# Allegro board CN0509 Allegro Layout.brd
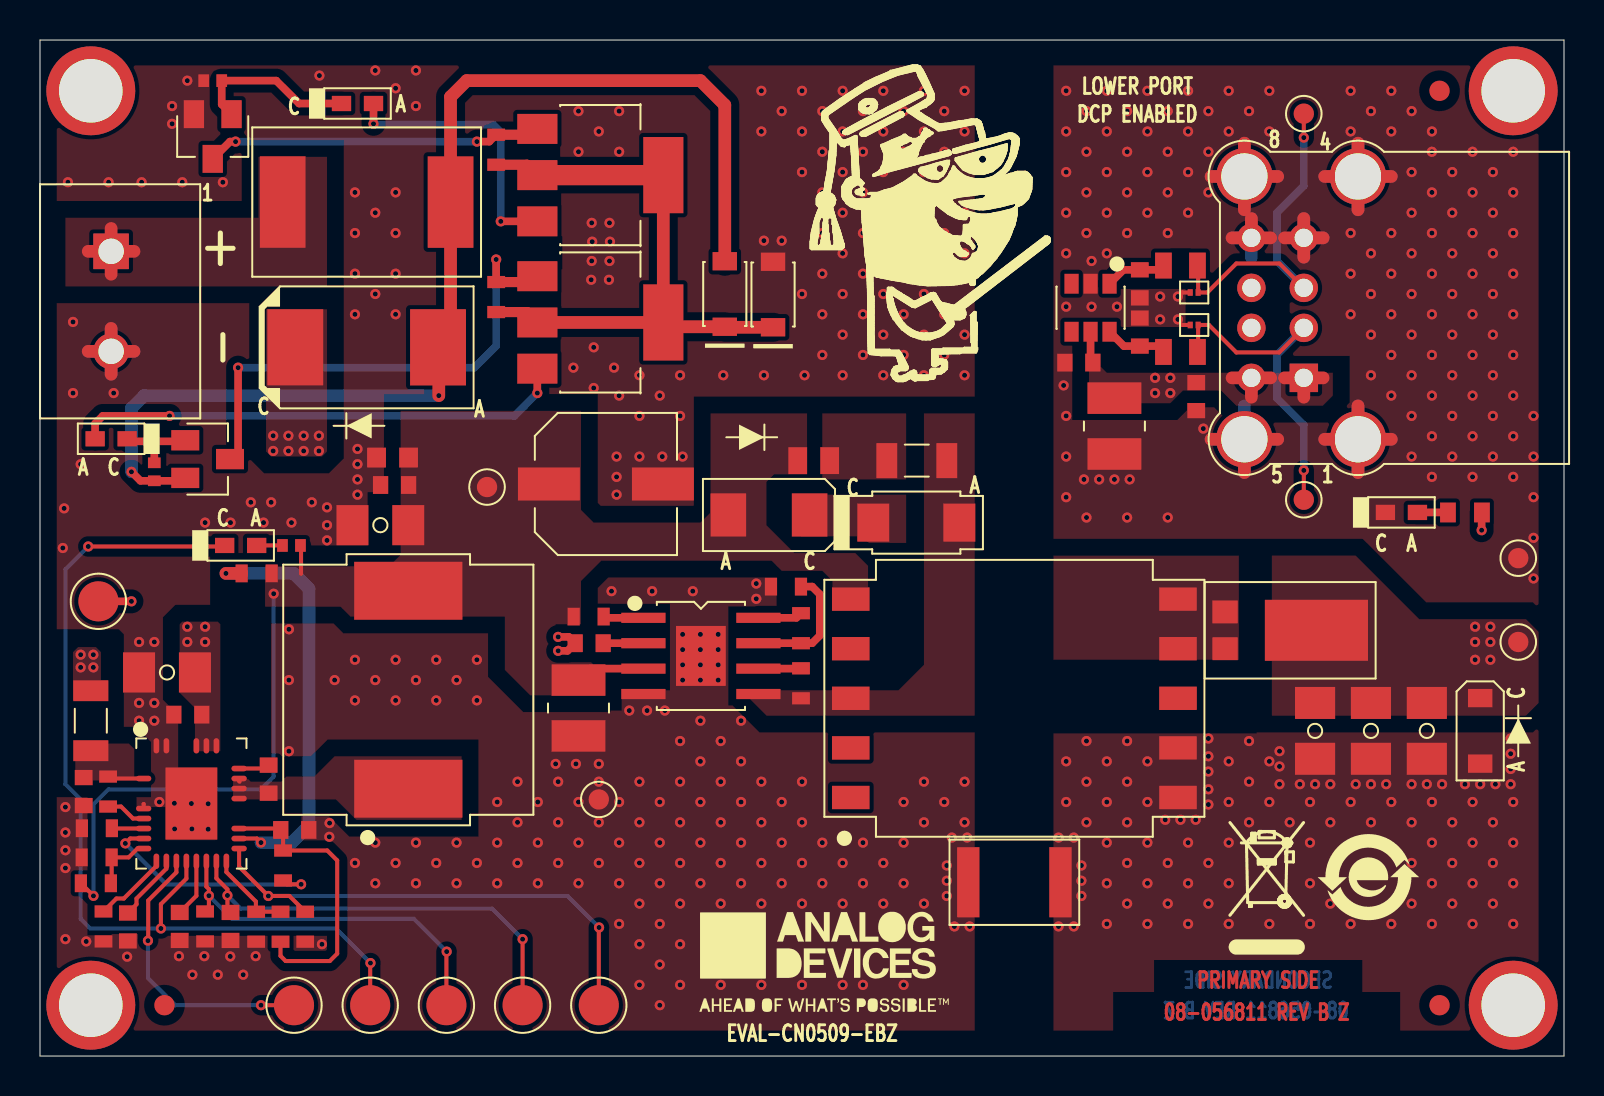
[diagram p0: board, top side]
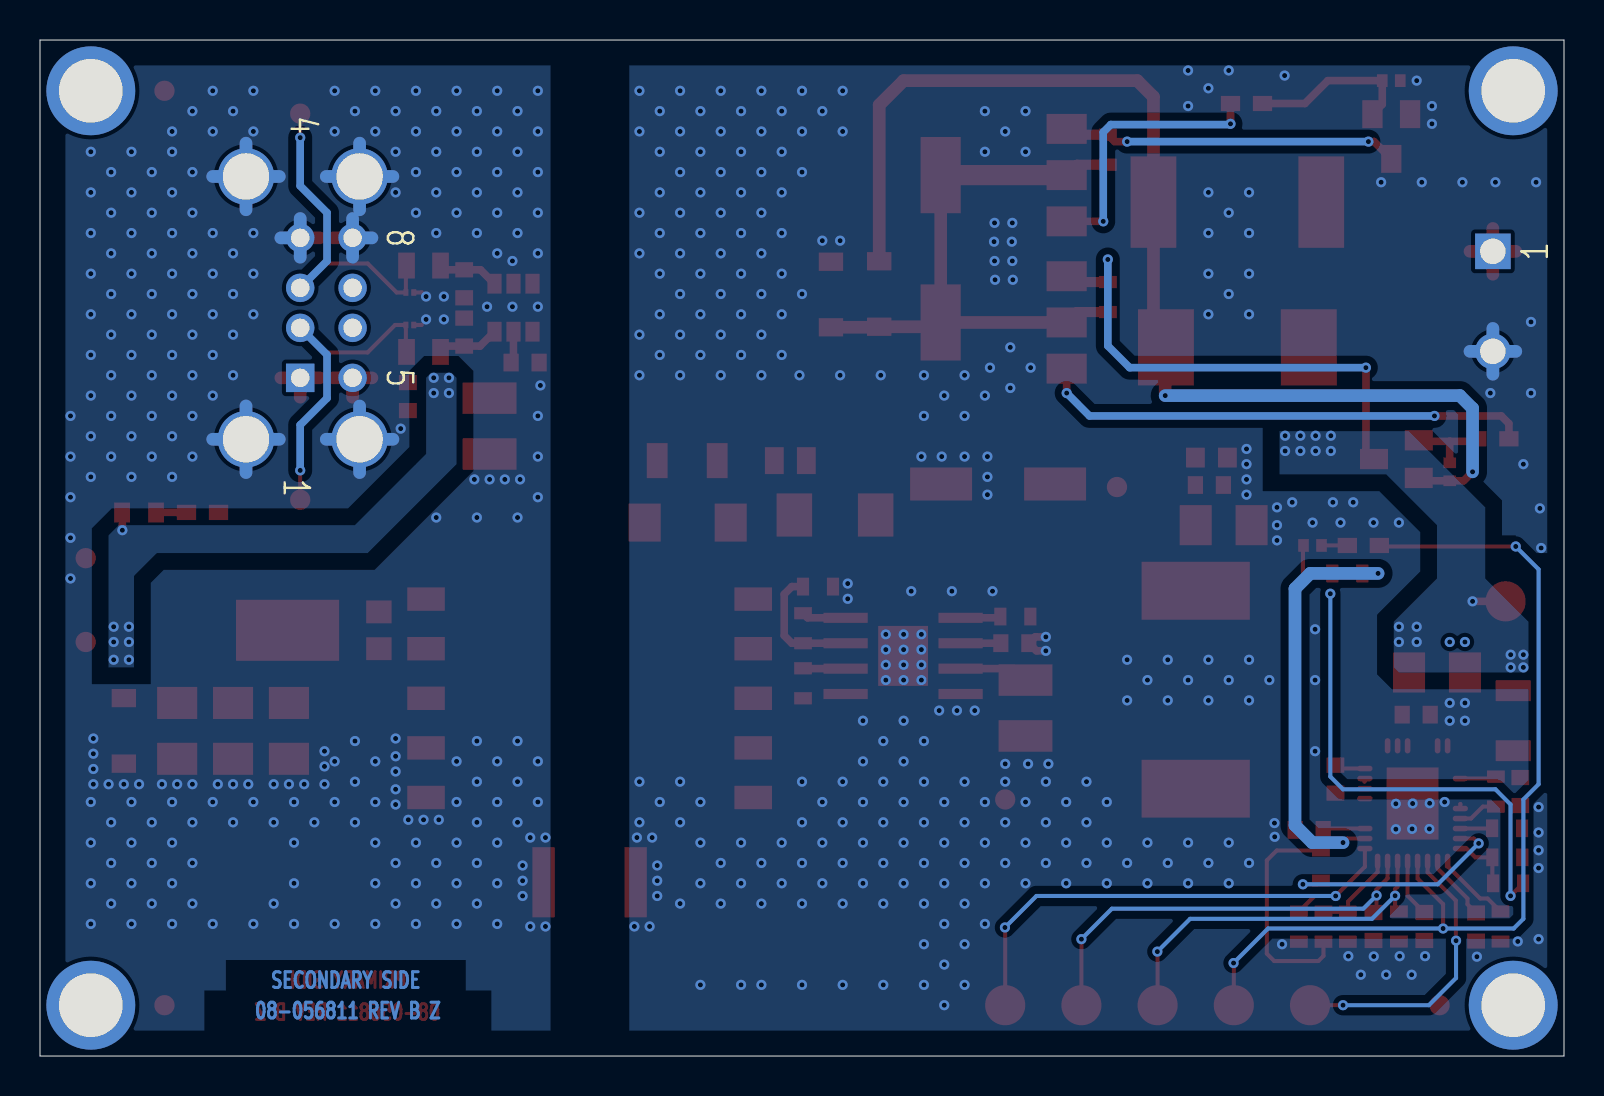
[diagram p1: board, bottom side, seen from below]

Outline 76.2 x 50.8 mm; copper layers: TOP, L2_GND, L3_GND, BOTTOM. Coordinates in mm from the lower left corner of the outline.
Outline path: 0,50.8 0,0 76.2,0 76.2,50.8 0,50.8

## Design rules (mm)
constraint set DEFAULT: min track width 0.203

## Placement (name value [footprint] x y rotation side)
C1  1uF  [C0603]  12.74 11.3 180 top
C2  4.7uF  [C1206H71]  6.35 19.18 0 top
C3  0.1uF  [C0603]  11.43 13.84 90 top
C4  0.1uF  [C0603]  7.39 17.07 0 top
C5  0.1uF  [C0603]  4.39 6.45 90 top
C6  22uF  [CPLSMSQ260H315]  28.3 28.6 0 top
C7  10uF  [C1210-2]  26.92 17.4 90 top
C8  100uF  [C1206H71]  17.02 26.54 0 top
C9  0.1uF  [C0603]  17.73 28.55 0 top
C10  0.1uF  [C0603]  9.53 6.48 90 top
C11  1uF  [C0603#2]  17.63 29.92 0 top
C12  0.1uF  [C0603]  6.99 6.48 90 top
C13  0.1uF  [C0603]  2.18 13.22 90 top
C14  1uF  [C0603]  27.46 20.64 0 top
C15  220pF  [C0805]  38.68 29.77 180 top
C16  100uF  [C1206H71]  63.75 16.26 90 top
C17  100uF  [C1206H71]  66.55 16.26 90 top
C18  100uF  [C1206H71]  69.34 16.26 90 top
C19  4700pF  [C1812H79]  48.72 8.69 0 top
C20  10uF  [C1210-2]  53.72 31.5 90 top
C21  0.01uF  [C0603]  51.94 34.67 0 top
C22  1000pF  [C0603]  54.99 38.61 90 top
C23  1000pF  [C0603]  54.99 36.2 270 top
C24  1uF  [C0603]  57.81 32.97 90 top
CLKOUT  SMOX/060/B1/R2K GOLD  [CNOXLEYSMOX_060_B1]  12.7 2.54 0 top
D1  PDS1040L  [POWERDI5]  62.51 21.28 270 top
D2  SMD1200PL-TP  [SOD123FLH53]  36.65 38.07 90 top
D3  SMAJ18A-13-F  [DO214AC]  36.45 27.05 180 top
D4  SS110FL-TP  [DO221AC_SMA-FL]  43.81 26.67 0 top
D5  MMSZ5232B-7-F  [SOD123-2]  72.01 16.26 270 top
D6  SMD1200PL-TP  [SOD123FLH53]  34.24 38.1 90 top
D7  MBRS3201T3G  [SMC]  16.33 35.43 0 top
D8  ESD230B1W0201E6327XTSA1  [D0201H6]  57.71 36.55 0 top
D9  ESD230B1W0201E6327XTSA1  [D0201H6]  57.71 38.18 0 top
D+  TESTPAD  [TPSMC40]  63.19 47.12 0 top
D-  TESTPAD  [TPSMC40]  63.19 27.81 0 top
DS1  LTST-C190CKT  [LED0603]  3.56 30.86 180 top
DS2  LTST-C190GKT  [LED0603]  15.88 47.62 0 top
DS3  LTST-C190GKT  [LED0603]  10.03 25.53 0 top
DS4  LTST-C190GKT  [LED0603]  68.07 27.18 0 top
F1  2.5A  [SMD250F]  16.33 42.7 0 top
GND  TESTPAD  [TPSMC40]  73.91 24.89 0 top
GND1  TESTPAD  [TPSMC40]  27.94 12.83 0 top
ICTRL  SMOX/060/B1/R2K GOLD  [CNOXLEYSMOX_060_B1]  20.32 2.54 0 top
IMON  SMOX/060/B1/R2K GOLD  [CNOXLEYSMOX_060_B1]  24.13 2.54 0 top
L1  47UH  [LSMSQ472H394]  18.41 18.31 90 top
NOREF  -  []  0 50.8 0 top
NOREF#2  -  []  0 50.8 0 top
NOREF#3  -  [unnamed#2]  2.54 2.54 0 top
NOREF#4  -  []  0 0 0 top
NOREF#5  -  []  38.91 4.67 0 top
NOREF#6  -  []  76.2 0 0 top
NOREF#7  -  []  74.43 49.27 0 top
NOREF#8  -  []  -63.5 226.06 0 top
NOREF#9  -  []  2.54 2.54 0 top
NOREF#10  -  []  0 50.8 270 top
NOREF#11  -  []  32.21 -14.22 270 top
NOREF#12  -  [unnamed#2]  69.98 2.54 0 top
NOREF#13  -  []  0 0 0 top
NOREF#14  -  []  -86.36 181.61 0 top
NOREF#15  -  []  61.14 5.13 0 top
NOREF#16  -  [unnamed#2]  73.66 2.54 0 top
NOREF#17  -  [unnamed#2]  6.22 2.54 0 top
NOREF#18  -  []  0 0 0 top
NOREF#19  -  []  2.54 2.54 0 top
NOREF#20  -  [unnamed#2]  2.54 48.26 0 top
NOREF#21  -  []  -42.55 -32 0 top
NOREF#22  -  []  -124.46 -144.78 0 top
NOREF#23  -  []  132.97 172.34 0 top
NOREF#24  -  []  -124.46 -144.78 0 top
NOREF#25  -  []  76.2 50.8 180 top
NOREF#26  -  []  76.2 0 90 top
NOREF#27  -  []  76.2 0 90 top
NOREF#28  -  [unnamed#2]  69.98 48.26 0 top
NOREF#29  -  []  66.42 8.94 0 top
NOREF#30  -  []  115.57 44.7 0 top
NOREF#31  -  [unnamed#2]  73.66 48.26 0 top
NOREF#32  -  []  -124.46 -144.78 0 top
NOREF#33  -  []  280.77 319.28 0 top
NOREF#34  -  []  76.2 40.95 0 top
P1  OSTTC020162  [CNOSTTC0201X2]  3.56 40.23 270 top
P2  UJ2-ADH-1-TH  [CNCUIUJ2-ADH-X-TH]  63.19 33.91 90 top
PGOOD  SMOX/060/B1/R2K GOLD  [CNOXLEYSMOX_060_B1]  16.51 2.54 0 top
Q1  MMBT3904LT1G  [SOT23]  8.64 45.97 180 top
Q2  MMBT3904LT1G  [SOT23]  8.38 29.84 270 top
Q3  DZTA42-13  [SOT223-3]  28.02 44.04 270 top
Q4  DZTA42-13  [SOT223-3]  28.02 36.68 270 top
R1  270K  [R0603]  22.81 45.31 270 top
R2  240  [R0603#2]  8.64 48.77 0 top
R3  270K  [R0603]  22.81 37.95 270 top
R4  240  [R0603#2]  5.71 29.21 90 top
R5  0  [R0603]  12.03 6.46 90 top
R6  0  [R0603]  10.81 6.46 270 top
R7  10MEG  [R1206]  2.54 16.76 90 top
R8  0  [R0603]  12.15 9.53 270 top
R9  0  [R0603]  10.83 24.13 0 top
R10  0  [R0603]  3.4 13.22 90 top
R11  0  [R0603]  3.17 6.48 90 top
R12  0  [R0603]  2.79 8.64 180 top
R13  0  [R0603]  2.83 9.93 180 top
R14  10K  [R0603]  37.3 23.47 0 top
R15  1MEG  [R0603]  27.43 21.97 180 top
R16  0  [R0603]  2.84 11.39 180 top
R17  0  [R0603]  8.25 6.48 270 top
R18  0  [R0603]  13.26 6.46 270 top
R19  100  [R1206]  43.84 29.77 180 top
R20  158K  [R0603]  38.05 18.63 90 top
R21  113K  [R0603]  38.05 21.39 270 top
R22  24  [R0805]  57.02 35.2 0 top
R23  24  [R0805]  57.02 39.52 0 top
R24  3.48K  [R0603#2]  12.57 25.53 0 top
R25  2.1K  [R0603]  71.25 27.18 0 top
T1  750311564  [TSMSQ525H500]  48.72 17.88 0 top
TP1  SMOX/060/B1/R2K GOLD  [CNOXLEYSMOX_060_B1]  27.94 2.54 0 top
TP6  SMOX/060/B1/R2K GOLD  [CNOXLEYSMOX_060_B1]  2.92 22.73 0 top
U1  LTC7103EUHE#PBF  [QFN36_5X6_PAD2_6X3_6]  7.57 12.62 270 top
U2  LT8302IS8E#PBF  [SO8NB_PAD3X2_49]  33.05 20 270 top
U3  TPS2514DBVR  [SOT23_6-2]  52.53 37.41 180 top
UNK12V  TESTPAD  [TPSMC40]  22.35 28.45 0 top
VBUS  TESTPAD  [TPSMC40]  73.91 20.7 0 top

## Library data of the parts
C1 C11 C14 C24 = CAP: User Part Number: UPN; Tolerance: 10; alternate symbols: C0603L; part number: CAP_SM-1UF,50V,10,E034224,C0603; tolerance: 10
C2 = CAP: Tolerance: 10; User Part Number: UPN; alternate symbols: (); part number: CAP_SM-4.7UF,100V,10,E034771,C1206H71; tolerance: 10
C3-C5 C9 C10 C12 C13 = CAP: User Part Number: UPN; Tolerance: 10; alternate symbols: C0603L; part number: CAP_SM-0.1UF,100V,10,E033337,C0603; tolerance: 10
C6 = CAPP: Tolerance: 20; User Part Number: UPN; alternate symbols: (); part number: CAPP_SM-22UF,63V,20,E034289,CPLSMSQ260H315; tolerance: 20
C7 C20 = CAP: Tolerance: 10; User Part Number: UPN; alternate symbols: (); part number: CAP_SM-10UF,50V,10,E038290,C1210-2; tolerance: 10
C8 C16-C18 = CAP: Tolerance: 10; User Part Number: UPN; alternate symbols: (); part number: CAP_SM-100UF,6.3V,10,E039989,C1206H71; tolerance: 10
C15 = CAP: User Part Number: UPN; Tolerance: 5; alternate symbols: C0805L; part number: CAP_SM-220PF,50V,5,E000453,C0805; tolerance: 5
C19 = CAP: Tolerance: 10; User Part Number: UPN; alternate symbols: (); part number: CAP_SM-4700PF,150V,10,E039988,C1812H79; tolerance: 10
C21 = CAP: User Part Number: UPN; Tolerance: 10; alternate symbols: C0603L; part number: CAP_SM-0.01UF,100V,10,E032297,C0603; tolerance: 10
C22 C23 = CAP: User Part Number: UPN; Tolerance: 10; alternate symbols: C0603L; part number: CAP_SM-1000PF,50V,10,E013782,C0603; tolerance: 10
CLKOUT ICTRL IMON PGOOD TP1 TP6 = CNTP1P: Tolerance: N/A; User Part Number: UPN; alternate symbols: (); part number: CNTP1P_SM-GOLD,E023771,CNOXLEYSMOX_060_B1; tolerance: N/A
D1 = DIOSCHOTTKY_3P: Tolerance: N/A; User Part Number: UPN; alternate symbols: (); part number: DIOSCHOTTKY_3P_SM-PDS1040L,40V,N/A,E006430,POWERDI5; tolerance: N/A
D2 D6 = DIOSCHOTTKY: User Part Number: UPN; Tolerance: N/A; alternate symbols: (); part number: DIOSCHOTTKY_SM-SMD1200PL-TP,200V,N/A,E042391,SOD123FLH53; tolerance: N/A
D3 = DIO: User Part Number: UPN; Tolerance: N/A; alternate symbols: (); part number: DIO_SM-SMAJ18A-13-F,N/A,N/A,E006682,DO214AC; tolerance: N/A
D4 = DIOSCHOTTKY: User Part Number: UPN; Tolerance: N/A; alternate symbols: (); part number: DIOSCHOTTKY_SM-SS110FL-TP,100V,N/A,E039987,DO221AC_SMA-FL; tolerance: N/A
D5 = DIOZNR: User Part Number: UPN; Tolerance: N/A; alternate symbols: (); part number: DIOZNR_SM-MMSZ5232B-7-F,5.6V,N/A,E039990,SOD123-2; tolerance: N/A
D7 = DIOSCHOTTKY: User Part Number: UPN; Tolerance: N/A; alternate symbols: (); part number: DIOSCHOTTKY_SM-MBRS3201T3G,200V,N/A,E014312,SMC; tolerance: N/A
D8 D9 = DIOZNR_V2: User Part Number: UPN; Tolerance: N/A; alternate symbols: (); part number: DIOZNR_V2_SM-ESD230B1W0201E6327XTSA1,5.5V,N/A,E040149,D0201H6; tolerance: N/A
D+ D- GND GND1 UNK12V VBUS = NCTESTPAD: Tolerance: N/A; User Part Number: UPN; alternate symbols: (); part number: NCTESTPAD_SM-TESTPAD,E019801,TPSMC40; tolerance: N/A
DS1 = DIOLED: Tolerance: N/A; User Part Number: UPN; alternate symbols: (); part number: DIOLED_SM-LTST-C190CKT,N/A,N/A,E023763,LED0603; tolerance: N/A
DS2-DS4 = DIOLED: Tolerance: N/A; User Part Number: UPN; alternate symbols: (); part number: DIOLED_SM-LTST-C190GKT,N/A,N/A,E006239,LED0603; tolerance: N/A
F1 = FSFUSE: Tolerance: N/A; User Part Number: UPN; alternate symbols: (); part number: FSFUSE_SM-2.5A,15V,E006334,SMD250F; tolerance: N/A
L1 = IND: Tolerance: 20; User Part Number: UPN; alternate symbols: (); part number: IND_SM-47UH,20,E041207,LSMSQ472H394; tolerance: 20
P1 = CN2P: Tolerance: N/A; User Part Number: UPN; alternate symbols: (); part number: CN2P_TH-OSTTC020162,E034806,CNOSTTC0201X2; tolerance: N/A
P2 = CN8P_4PSHLD: User Part Number: UPN; Tolerance: N/A; alternate symbols: (); part number: CN8P_4PSHLD_TH-UJ2-ADH-1-TH,E039589,CNCUIUJ2-ADH-X-TH; tolerance: N/A
Q1 Q2 = TRANMMBT4401: User Part Number: UPN; Tolerance: N/A; alternate symbols: (); part number: TRANMMBT4401_SM-MMBT3904LT1G,E004664,SOT23; tolerance: N/A
Q3 Q4 = TRANNPN_4P_V2: User Part Number: UPN; Tolerance: N/A; alternate symbols: (); part number: TRANNPN_4P_V2_SM-DZTA42-13,E039574,SOT223-3; tolerance: N/A
R1 R3 = RES: User Part Number: UPN; Tolerance: 1; alternate symbols: R0603L; part number: RES_SM-270K,E013325,1/10W,1,R0603; tolerance: 1
R2 R4 = RES: User Part Number: UPN; Tolerance: 1; alternate symbols: R0402L; part number: RES_SM-240,E044225,1/10W,1,R0603; tolerance: 1
R5 R6 R8-R13 R16-R18 = RES: User Part Number: UPN; Tolerance: JUMPER; alternate symbols: R0603L; part number: RES_SM-0,E006826,1/10W,JUMPER,R0603; tolerance: JUMPER
R7 = RES: User Part Number: UPN; Tolerance: 1; alternate symbols: (); part number: RES_SM-10MEG,E016426,1/4W,1,R1206; tolerance: 1
R14 = RES: User Part Number: UPN; Tolerance: 1; alternate symbols: R0603L; part number: RES_SM-10K,E003671,1/10W,1,R0603; tolerance: 1
R15 = RES: User Part Number: UPN; Tolerance: 1; alternate symbols: R0603L; part number: RES_SM-1MEG,E003682,1/10W,1,R0603; tolerance: 1
R19 = RES: User Part Number: UPN; Tolerance: 1; alternate symbols: (); part number: RES_SM-100,E003220,1/4W,1,R1206; tolerance: 1
R20 = RES: User Part Number: UPN; Tolerance: 1; alternate symbols: R0603L; part number: RES_SM-158K,E028116,1/10W,1,R0603; tolerance: 1
R21 = RES: User Part Number: UPN; Tolerance: 1; alternate symbols: R0603L; part number: RES_SM-113K,E021374,1/10W,1,R0603; tolerance: 1
R22 R23 = RES: User Part Number: UPN; Tolerance: 1; alternate symbols: R0805L; part number: RES_SM-24,E031456,1/8W,1,R0805; tolerance: 1
R24 = RES: User Part Number: UPN; Tolerance: 1; alternate symbols: R0402L; part number: RES_SM-3.48K,E003694,1/10W,1,R0603; tolerance: 1
R25 = RES: User Part Number: UPN; Tolerance: 1; alternate symbols: (R0603L); part number: RES_SM-2.1K,E011132,1/10W,1,R0603; tolerance: 1
T1 = XFMR10P_V14: User Part Number: UPN; Tolerance: N/A; alternate symbols: (); part number: XFMR10P_V14_SM-750311564,E039577,TSMSQ525H500; tolerance: N/A
U1 = ICLTC7103: Tolerance: N/A; User Part Number: UPN; alternate symbols: (); part number: ICLTC7103_SM-LTC7103EUHE#PBF,E033167,QFN36_5X6_PAD2_6X3_6; tolerance: N/A
U2 = LINLT8302: Tolerance: N/A; User Part Number: UPN; alternate symbols: (); part number: LINLT8302_SM-LT8302IS8E#PBF,E031116,SO8NB_PAD3X2_49; tolerance: N/A
U3 = ICTPS2514: User Part Number: UPN; Tolerance: N/A; alternate symbols: (); part number: ICTPS2514_SM-TPS2514DBVR,E035630,SOT23_6-2; tolerance: N/A

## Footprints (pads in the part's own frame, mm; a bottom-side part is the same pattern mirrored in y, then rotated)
C0603
  rect 0.762x0.889 smd: 1(-0.7,0) 2(0.7,0)
C0603#2
  rect 0.94x0.991 smd: 1(-0.8,0) 2(0.8,0)
C0805
  rect 0.94x1.346 smd: 1(-0.8,0) 2(0.8,0)
C1206H71
  rect 1.6x2.007 smd: 1(-1.397,0) 2(1.397,0)
C1210-2
  rect 1.575x2.692 smd: 1(-1.397,0) 2(1.397,0)
C1812H79
  rect 1.118x3.505 smd: 1(-2.304,0) 2(2.304,0)
CNCUIUJ2-ADH-X-TH
  rect 1.422x1.422 hole 0.914: 1(0,0)
  round 1.422 hole 0.914: 2(2.5,0) 3(4.5,0) 4(7,0) 5(0,2.62) 6(2.5,2.62) 7(4.5,2.62) 8(7,2.62)
  round 2.819 hole 2.311: SH1(-3.07,-2.71) SH2(10.07,-2.71) SH3(-3.07,2.97) SH4(10.07,2.97)
CNOSTTC0201X2
  rect 1.778x1.778 hole 1.27: 1(0,0)
  round 1.778 hole 1.27: 2(5,0)
CNOXLEYSMOX_060_B1
  round 2.007 smd: 1(0,0)
CPLSMSQ260H315
  rect 3.099x1.651 smd: N(2.85,0) P(-2.85,0)
D0201H6
  rect 0.254x0.33 smd: 1(-0.197,0) 2(0.197,0)
DO214AC
  rect 1.778x2.159 smd: A(2.032,0) C(-2.032,0)
DO221AC_SMA-FL
  rect 1.6x1.905 smd: A(2.15,0) C(-2.15,0)
LED0603
  rect 0.965x0.762 smd: A(0.8,0) C(-0.8,0)
LSMSQ472H394
  rect 2.896x5.41 smd: 1(-4.948,0) 2(4.948,0)
POWERDI5
  rect 1.143x1.27 smd: 1(-0.92,-3.255) 2(0.92,-3.255)
  rect 3.048x5.156 smd: 3(0,1.312)
QFN36_5X6_PAD2_6X3_6
  oval 0.279x0.762 smd: 3(-1.25,-2.386) 6(0.25,-2.386) 7(0.75,-2.386) 8(1.25,-2.386) 9(1.75,-2.386) 10(2.25,-2.386) 19(2.25,2.386) 20(1.75,2.386) 21(1.25,2.386) 24(-0.25,2.386) 25(-0.75,2.386) 26(-1.25,2.386) 27(-1.75,2.386)
  oval 0.762x0.279 smd: 11(2.886,-1.75) 12(2.886,-1.25) 13(2.886,-0.75) 14(2.886,-0.25) 15(2.886,0.25) 16(2.886,0.75) 17(2.886,1.25) 18(2.886,1.75) 30(-2.886,1.25) 31(-2.886,0.75) 32(-2.886,0.25) 35(-2.886,-1.25) 36(-2.886,-1.75)
  rect 3.607x2.591 smd: PAD(0,0)
R0603
  rect 0.61x0.889 smd: 1(-0.75,0) 2(0.75,0)
R0603#2
  rect 0.533x0.635 smd: 1(-0.45,0) 2(0.45,0)
R0805
  rect 0.838x1.295 smd: 1(-0.85,0) 2(0.85,0)
R1206
  rect 1.041x1.753 smd: 1(-1.5,0) 2(1.5,0)
SMC
  rect 2.794x3.81 smd: A(3.569,0) C(-3.569,0)
SMD250F
  rect 2.286x4.572 smd: 1(-4.196,0) 2(4.196,0)
SO8NB_PAD3X2_49
  rect 0.508x2.21 smd: 1(-1.905,-2.875) 2(-0.635,-2.875) 3(0.635,-2.875) 4(1.905,-2.875) 5(1.905,2.875) 6(0.635,2.875) 7(-0.635,2.875) 8(-1.905,2.875)
  rect 2.997x2.489 smd: PAD(0,0)
SOD123-2
  rect 0.914x1.219 smd: A(1.638,0) C(-1.638,0)
SOD123FLH53
  rect 0.914x1.219 smd: A(1.638,0) C(-1.638,0)
SOT23
  rect 1.016x1.397 smd: 1(-0.94,-1.118) 2(0.94,-1.118) 3(0,1.118)
SOT23_6-2
  rect 0.711x0.991 smd: 1(-0.95,-1.2) 2(0,-1.2) 3(0.95,-1.2) 4(0.95,1.2) 5(0,1.2) 6(-0.95,1.2)
SOT223-3
  rect 1.499x2.007 smd: 1(-2.311,-3.15) 2(0,-3.15) 3(2.311,-3.15)
  rect 3.81x2.007 smd: 4(0,3.15)
TPSMC40
  round 1.016 smd: 1(0,0)
TSMSQ525H500
  rect 1.88x1.168 smd: 1(-8.18,-4.96) 2(-8.18,-2.48) 3(-8.18,0) 4(-8.18,2.48) 5(-8.18,4.96) 6(8.18,4.96) 7(8.18,2.48) 8(8.18,0) 9(8.18,-2.48) 10(8.18,-4.96)
unnamed#2
  round 4.445 hole 3.175 unplated: (0,0)

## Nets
GND: C1.1 C2.1 C4.1 C5.1 C6.N(N2) C7.1 C8.1 C9.1 C10.1 C11.1 C12.1 C13.1 C14.1 C19.1 D2.A(P) GND1.1(N1) P1.2(N2) Q1.2(E) R2.1 R6.2(N2) R11.1 R13.2(N2) R14.1 R16.2(N2) R17.2(N2) R18.2(N2) U1.6 U1.35 U1.36 U1.PAD U2.4 U2.PAD
PGND: C16.1 C17.1 C18.1 C19.2(N2) C20.1 C21.1 C22.1 C23.1 C24.1 D5.A(P) D8.1 D9.1 DS4.C GND.1(N1) P2.4 P2.8 P2.SH1(N9) P2.SH2 P2.SH3 P2.SH4 T1.9 T1.10 U3.2
VIN: C2.2(N2) C4.2(N2) D7.C R7.2(N2) TP6.1(N1) U1.30 U1.31 U1.32
BOOST: C3.1 L1.1 U1.24 U1.25 U1.26
INTVCC: C1.2(N2) R5.1 R8.1 U1.21
PGOOD: DS3.C PGOOD.1(N1) U1.14
UNNAMED_2_CAP_I32_N2: C3.2(N2) U1.27
UNNAMED_2_CAP_I45_N2: C13.2(N2) R7.1 R10.2(N2) U1.3
UNNAMED_2_CAP_I46_N2: C12.2(N2) U1.15
UNNAMED_2_CAP_I48_N2: C5.2(N2) U1.12
UNNAMED_2_CAP_I51_N2: C10.2(N2) IMON.1(N1) U1.17
UNNAMED_2_CAP_I80_N2: C14.2(N2) U2.2
UNNAMED_2_CAP_I86_N1: C15.1 R19.2(N2)
UNNAMED_2_CAP_I131_N2: C22.2(N2) R23.1 U3.1
UNNAMED_2_CAP_I132_N2: C23.2(N2) R22.1 U3.6
UNNAMED_2_CN8P4PSHLD_I107_N2: D8.2(N2) D-.1(N1) P2.2 R22.2(N2)
UNNAMED_2_CN8P4PSHLD_I107_N3: D9.2(N2) D+.1(N1) P2.3 R23.2(N2)
UNNAMED_2_CNTP1P_I34_N1: R18.1 TP1.1(N1) U1.19(VPRG2)
UNNAMED_2_CNTP1P_I36_N1: CLKOUT.1(N1) U1.13
UNNAMED_2_DIO_I82_N: D3.C D4.C
UNNAMED_2_DIOLED_I7_N: DS2.C Q1.1 R2.2(N2)
UNNAMED_2_DIOLED_I7_P: DS2.A(P) Q3.3(E)
UNNAMED_2_DIOLED_I17_N: DS1.C Q2.1 R4.2(N2)
UNNAMED_2_DIOLED_I17_P: DS1.A(P) Q4.3(E)
UNNAMED_2_DIOLED_I148_P: DS3.A(P) R24.1
UNNAMED_2_DIOLED_I151_P: DS4.A(P) R25.1
UNNAMED_2_DIOSCHOTTKY3P_I89_A1: D1.1 D1.2 T1.6 T1.7(SEC_DOT_2)
UNNAMED_2_DIOSCHOTTKY_I83_P: D4.A(P) R19.1 R20.1 T1.3 U2.5
UNNAMED_2_DIOSCHOTTKY_I97_P: D6.A(P) D7.A(P) F1.2(N2) Q2.2(E) R4.1
UNNAMED_2_ICLTC7103_I1_EXTVCC: R9.1 U1.20
UNNAMED_2_ICLTC7103_I1_FREQ: R11.2(N2) U1.11
UNNAMED_2_ICLTC7103_I1_ICTRL: ICTRL.1(N1) R17.1 U1.16
UNNAMED_2_ICLTC7103_I1_ITH: R8.2(N2) U1.9
UNNAMED_2_ICLTC7103_I1_OVLO: R10.1 U1.7
UNNAMED_2_ICLTC7103_I1_RIND: R16.1 U1.8
UNNAMED_2_ICLTC7103_I1_VFB: R12.1 R13.1 U1.10
UNNAMED_2_ICLTC7103_I1_VPRG1: R5.2(N2) R6.1 U1.18
UNNAMED_2_LINLT8302_I70_EN: R15.1 U2.1
UNNAMED_2_LINLT8302_I70_RFB: R20.2(N2) U2.6
UNNAMED_2_LINLT8302_I70_RREF: R14.2(N2) R21.2(N2) U2.7
UNNAMED_2_LINLT8302_I70_TC: R21.1 U2.8
UNNAMED_2_RES_I9_N1: Q1.3 Q3.1 R1.1
UNNAMED_2_RES_I19_N1: Q2.3 Q4.1 R3.1
UNNAMED_2_RES_I19_N2: D2.C D6.C Q3.2 Q3.4 Q4.2 Q4.4 R1.2(N2) R3.2(N2)
V_ENTRY: F1.1 P1.1
VOUT: C16.2(N2) C17.2(N2) C18.2(N2) C20.2(N2) C21.2(N2) C24.2(N2) D1.3(C) D5.C P2.1 P2.5 R25.2(N2) U3.5 VBUS.1(N1)
VOUT_7103: C6.P C7.2(N2) C8.2(N2) C9.2(N2) C11.2(N2) C15.2(N2) D3.A(P) L1.2(N2) R9.2(N2) R12.2(N2) R15.2(N2) R24.2(N2) T1.5 U2.3(VIN) UNK12V.1

Pads without a net: P2 6 7; T1 1 2 4 8; U3 3 4

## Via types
v1: diameter 0.508, hole 0.254, TOP to BOTTOM, 614 vias

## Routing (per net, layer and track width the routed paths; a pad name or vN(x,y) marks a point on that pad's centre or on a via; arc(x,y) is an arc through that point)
GND: length 20.5
  TOP w0.203: U1.6 5.18,12.6 5.18,12.6
  TOP w0.381: v1(25.91,20.26) 26.38,20.26 C14.1 26.44,20.95 v1(25.91,20.95)
  TOP w0.635: 2.41,35.23 P1.2 ; P1.2 4.7,35.23 ; P1.2 3.56,34.09 ; P1.2 3.56,36.38
  L2_GND w0.635: 2.41,35.23 P1.2 ; P1.2 3.56,34.09 ; P1.2 4.7,35.23 ; P1.2 3.56,36.38
  L3_GND w0.635: 2.41,35.23 P1.2 ; P1.2 3.56,36.38 ; P1.2 3.56,34.09 ; P1.2 4.7,35.23
  BOTTOM w0.635: 2.41,35.23 P1.2 ; P1.2 3.56,36.38 ; P1.2 3.56,34.09 ; P1.2 4.7,35.23
  vias: v1(1.14,25.4) v1(1.21,27.38) v1(1.27,12.45) v1(1.27,11.18) v1(1.27,10.29) v1(1.27,9.4) v1(1.27,5.84) v1(1.4,43.69) v1(1.65,36.7) v1(1.65,33.15) v1(2.03,29.59) v1(2.31,5.73) v1(3.43,43.69) v1(3.68,33.15) v1(4.36,4.97) v1(4.95,20.7) v1(4.95,17.65) v1(4.95,16.76) v1(5.08,43.69) v1(5.71,20.7) v1(5.71,17.65) v1(5.71,16.76) v1(5.97,12.7) v1(6.6,47.5) v1(6.6,46.61) v1(6.72,12.64) v1(6.73,11.35) v1(6.95,4.99) v1(7.11,43.69) v1(7.37,48.77) v1(7.57,12.62) v1(7.59,11.35) v1(7.62,4.06) v1(8.25,26.67) v1(8.22,4.99) v1(8.41,12.61) v1(8.41,11.34) v1(8.89,4.06) v1(9.14,43.69) v1(9.53,26.67) v1(9.51,4.98) v1(10.16,4.06) v1(10.54,27.69) v1(10.78,4.99) v1(11.18,26.67) v1(11.56,27.69) v1(12.45,21.34) v1(12.45,18.8) v1(12.45,15.24) v1(12.57,26.67) v1(13.59,27.69) v1(13.97,49.02) v1(14.1,5.59) v1(14.35,27.43) v1(14.35,26.54) v1(14.35,25.78) v1(14.48,11.65) v1(14.47,10.96) v1(14.73,18.8) v1(15.75,43.18) v1(15.75,41.15) v1(15.75,39.12) v1(15.75,37.08) v1(15.75,19.81) v1(15.75,17.78) v1(15.75,9.65) v1(15.88,30.35) v1(15.88,29.59) v1(15.88,28.83) v1(15.88,28.07) v1(16.76,49.28) v1(16.76,42.16) v1(16.76,38.1) v1(16.76,18.8) v1(16.76,10.67) v1(16.76,8.64) v1(17.78,48.39) v1(17.78,43.18) v1(17.78,41.15) v1(17.78,39.12) v1(17.78,37.08) v1(17.78,19.81) v1(17.78,17.78) v1(17.78,9.65) v1(18.8,49.28) v1(18.8,47.5) v1(18.8,18.8) v1(18.8,10.67) v1(18.8,8.64) v1(19.81,19.81) v1(19.81,17.78) v1(19.81,9.65) v1(20.83,18.8) v1(20.83,10.67) v1(20.83,8.64) v1(21.84,19.81) v1(21.84,17.78) v1(21.84,9.65) v1(22.86,12.7) v1(22.86,10.67) v1(22.86,8.64) v1(23.88,13.72) v1(23.88,11.68) v1(23.88,9.65) v1(24.89,12.7) v1(24.89,10.67) v1(24.89,8.64) v1(25.78,14.61) v1(25.91,13.72) v1(25.91,11.68) v1(25.91,9.65) v1(26.67,34.42) v1(26.8,14.61) v1(26.92,47.24) v1(26.92,45.21) v1(26.92,12.7) v1(26.92,10.67) v1(26.92,8.64) v1(27.58,41.66) v1(27.58,39.75) v1(27.56,38.81) v1(27.61,40.72) v1(27.69,35.43) v1(27.69,33.4) v1(27.94,46.23) v1(27.94,14.61) v1(27.94,13.72) v1(27.94,11.68) v1(27.94,9.65) v1(28.47,41.66) v1(28.47,39.75) v1(28.45,38.81) v1(28.5,40.72) v1(28.57,23.24) v1(28.7,34.42) v1(28.83,29.97) v1(28.83,28.96) v1(28.83,28.07) v1(28.96,47.24) v1(28.96,45.21) v1(28.96,33.02) v1(28.96,12.7) v1(28.96,10.67) v1(28.96,8.64) v1(28.96,6.6) v1(29.46,17.27) v1(29.97,34.04) v1(29.97,32) v1(29.97,29.97) v1(29.97,13.72) v1(29.97,11.68) v1(29.97,9.65) v1(29.97,7.62) v1(29.97,5.59) v1(29.97,3.56) v1(30.35,17.27) v1(30.61,23.24) v1(30.99,33.02) v1(30.99,12.7) v1(30.99,10.67) v1(30.99,8.64) v1(30.99,6.6) v1(30.99,4.57) v1(30.99,2.54) v1(31.11,29.97) v1(31.24,17.27) v1(32,34.04) v1(32,32) v1(32,15.75) v1(32,13.72) v1(32,11.68) v1(32,9.65) v1(32,7.62) v1(32,5.59) v1(32,3.56) v1(32.13,29.97) v1(32.13,21.08) v1(32.13,20.32) v1(32.13,19.56) v1(32.13,18.8) v1(32.64,23.24) v1(33.02,21.08) v1(33.02,20.32) v1(33.02,19.56) v1(33.02,18.8) v1(33.02,16.76) v1(33.02,14.73) v1(33.02,12.7) v1(33.02,10.67) v1(33.02,8.64) v1(33.91,21.08) v1(33.91,20.32) v1(33.91,19.56) v1(33.91,18.8) v1(34.04,15.75) v1(34.04,13.72) v1(34.04,11.68) v1(34.04,9.65) v1(34.04,7.62) v1(34.04,3.56) v1(34.16,34.04) v1(35.05,16.76) v1(35.05,14.73) v1(35.05,12.7) v1(35.05,10.67) v1(35.05,8.64) v1(35.81,23.62) v1(35.81,22.86) v1(36.07,48.26) v1(36.07,46.23) v1(36.07,13.72) v1(36.07,11.68) v1(36.07,9.65) v1(36.07,7.62) v1(36.07,3.56) v1(36.2,40.77) v1(36.2,34.04) v1(37.08,47.24) v1(37.08,40.77) v1(37.08,12.7) v1(37.08,10.67) v1(37.08,8.64) v1(38.1,48.26) v1(38.1,46.23) v1(38.1,44.2) v1(38.1,38.1) v1(38.1,13.72) v1(38.1,11.68) v1(38.1,9.65) v1(38.1,7.62) v1(38.1,3.56) v1(38.23,34.04) v1(39.12,47.24) v1(39.12,45.21) v1(39.12,43.18) v1(39.12,41.15) v1(39.12,39.12) v1(39.12,37.08) v1(39.12,35.05) v1(39.12,10.67) v1(39.12,8.64) v1(40.13,48.26) v1(40.13,46.23) v1(40.13,44.2) v1(40.13,42.16) v1(40.13,40.13) v1(40.13,38.1) v1(40.13,36.07) v1(40.13,34.04) v1(40.13,9.65) v1(40.13,7.62) v1(40.13,3.56) v1(41.15,47.24) v1(41.15,45.21) v1(41.15,43.18) v1(41.15,41.15) v1(41.15,39.12) v1(41.15,37.08) v1(41.15,35.05) v1(41.15,10.67) v1(41.15,8.64) v1(41.15,3.56) v1(42.16,48.26) v1(42.16,46.23) v1(42.16,44.2) v1(42.16,42.16) v1(42.16,40.13) v1(42.16,38.1) v1(42.16,36.07) v1(42.16,34.04) v1(42.16,9.65) v1(42.16,7.62) v1(43.18,47.24) v1(43.18,45.21) v1(43.18,43.18) v1(43.18,41.15) v1(43.18,39.12) v1(43.18,37.08) v1(43.18,35.05) v1(43.18,12.7) v1(43.18,10.67) v1(43.18,8.64) v1(43.18,3.56) v1(44.2,48.26) v1(44.2,46.23) v1(44.2,44.2) v1(44.2,42.16) v1(44.2,40.13) v1(44.2,38.1) v1(44.2,36.07) v1(44.2,34.04) v1(44.2,13.72) v1(44.2,11.68) v1(44.2,7.62) v1(45.21,47.24) v1(45.21,45.21) v1(45.21,43.18) v1(45.21,41.15) v1(45.21,39.12) v1(45.21,37.08) v1(45.21,35.05) v1(45.21,12.7) v1(45.34,9.53) v1(45.34,8.76) v1(45.34,8) v1(45.59,10.92) v1(45.72,6.48) v1(46.23,48.26) v1(46.23,46.23) v1(46.23,42.16) v1(46.23,40.13) v1(46.23,36.07) v1(46.23,34.04) v1(46.23,13.72) v1(46.23,11.68) v1(46.35,10.92) v1(46.48,6.48)
PGND: length 133.7
  TOP w0.203: D9.1 57.12,38.18 57.11,38.19 ; 57.11,36.56 57.12,36.55 D8.1
  TOP w0.635: P2.SH1 65.9,32.5 ; P2.SH1 65.9,29.17 ; P2.SH1 67.56,30.84 ; P2.SH1 64.24,30.84 ; P2.SH4 60.22,45.64 ; P2.SH4 60.22,42.31 ; P2.SH4 61.88,43.98 ; P2.SH4 58.56,43.98 ; 63.19,39.94 P2.4 ; P2.4 63.19,41.87 ; P2.4 62.22,40.91 ; P2.4 64.16,40.91 ; 65.9,42.31 P2.SH2 ; P2.SH2 67.56,43.98 ; P2.SH2 65.9,45.64 ; P2.SH2 64.24,43.98 ; 60.22,29.17 P2.SH3 ; P2.SH3 61.88,30.84 ; P2.SH3 58.56,30.84 ; 59.6,40.91 P2.8 ; P2.8 60.57,41.87 ; P2.8 61.54,40.91
  L2_GND w0.635: 63.19,39.94 P2.4 ; P2.4 64.16,40.91 ; P2.4 63.19,41.87 ; P2.4 62.22,40.91 ; 64.24,30.84 P2.SH1 ; P2.SH1 65.9,32.5 ; P2.SH1 67.56,30.84 ; P2.SH1 65.9,29.17 ; 60.22,42.31 P2.SH4 ; P2.SH4 61.88,43.98 ; P2.SH4 60.22,45.64 ; P2.SH4 58.56,43.98 ; 64.24,43.98 P2.SH2 ; P2.SH2 65.9,45.64 ; P2.SH2 67.56,43.98 ; P2.SH2 65.9,42.31 ; P2.SH3 60.22,32.5 ; P2.SH3 61.88,30.84 ; P2.SH3 58.56,30.84 ; P2.SH3 60.22,29.17 ; P2.8 60.57,41.87 ; P2.8 59.6,40.91 ; P2.8 61.54,40.91 ; P2.8 60.57,39.94
  L3_GND w0.635: P2.SH1 67.56,30.84 ; P2.SH1 65.9,32.5 ; P2.SH1 64.24,30.84 ; P2.SH1 65.9,29.17 ; 65.9,42.31 P2.SH2 ; P2.SH2 64.24,43.98 ; P2.SH2 65.9,45.64 ; P2.SH2 67.56,43.98 ; P2.SH4 61.88,43.98 ; P2.SH4 60.22,45.64 ; P2.SH4 60.22,42.31 ; P2.SH4 58.56,43.98 ; 62.22,40.91 P2.4 ; P2.4 63.19,41.87 ; P2.4 63.19,39.94 ; P2.4 64.16,40.91 ; P2.8 60.57,41.87 ; P2.8 59.6,40.91 ; P2.8 60.57,39.94 ; P2.8 61.54,40.91 ; P2.SH3 60.22,32.5 ; P2.SH3 60.22,29.17 ; P2.SH3 58.56,30.84 ; P2.SH3 61.88,30.84
  BOTTOM w0.635: P2.SH4 60.22,45.64 ; P2.SH4 60.22,42.31 ; P2.SH4 61.88,43.98 ; P2.SH4 58.56,43.98 ; 60.22,29.17 P2.SH3 ; P2.SH3 60.22,32.5 ; P2.SH3 58.56,30.84 ; P2.SH3 61.88,30.84 ; 64.24,30.84 P2.SH1 ; P2.SH1 67.56,30.84 ; P2.SH1 65.9,29.17 ; P2.SH1 65.9,32.5 ; 60.57,39.94 P2.8 ; P2.8 60.57,41.87 ; P2.8 59.6,40.91 ; 64.24,43.98 P2.SH2 ; P2.SH2 67.56,43.98 ; P2.SH2 65.9,42.31 ; P2.SH2 65.9,45.64 ; P2.4 63.19,41.87 ; P2.4 63.19,39.94 ; P2.4 64.16,40.91
  vias: v1(50.93,10.92) v1(50.93,6.48) v1(51.18,33.53) v1(51.31,48.26) v1(51.31,46.23) v1(51.31,44.2) v1(51.31,42.16) v1(51.31,40.13) v1(51.31,37.46) v1(51.31,32) v1(51.31,29.97) v1(51.31,27.94) v1(51.31,14.73) v1(51.31,12.7) v1(51.69,10.92) v1(51.69,6.48) v1(52.07,9.53) v1(52.07,8.76) v1(52.07,8) v1(52.2,28.83) v1(52.32,47.24) v1(52.32,45.21) v1(52.32,43.18) v1(52.32,41.15) v1(52.32,26.92) v1(52.32,15.75) v1(52.32,13.72) v1(52.32,11.68) v1(52.58,39.75) v1(52.58,37.46) v1(52.96,28.83) v1(53.34,48.26) v1(53.34,46.23) v1(53.34,44.2) v1(53.34,42.16) v1(53.34,40.13) v1(53.34,14.73) v1(53.34,12.7) v1(53.34,10.67) v1(53.34,8.64) v1(53.34,6.6) v1(53.72,28.83) v1(53.85,37.46) v1(54.36,47.24) v1(54.36,45.21) v1(54.36,43.18) v1(54.36,41.15) v1(54.36,26.92) v1(54.36,15.75) v1(54.36,13.72) v1(54.36,11.68) v1(54.36,9.65) v1(54.36,7.62) v1(54.48,28.83) v1(55.37,48.26) v1(55.37,46.23) v1(55.37,44.2) v1(55.37,42.16) v1(55.37,14.73) v1(55.37,12.7) v1(55.37,10.67) v1(55.37,8.64) v1(55.37,6.6) v1(56.01,37.97) v1(56.01,36.83) v1(56.26,11.81) v1(56.39,47.24) v1(56.39,45.21) v1(56.39,43.18) v1(56.39,41.15) v1(56.39,26.92) v1(56.39,9.65) v1(56.39,7.62) v1(56.9,37.97) v1(56.9,36.83) v1(57.02,11.81) v1(57.4,48.26) v1(57.4,46.23) v1(57.4,44.2) v1(57.4,42.16) v1(57.4,10.67) v1(57.4,8.64) v1(57.4,6.6) v1(57.78,11.81) v1(58.17,31.37) v1(58.42,47.24) v1(58.42,45.21) v1(58.42,43.18) v1(58.42,15.88) v1(58.42,14.99) v1(58.42,14.22) v1(58.42,13.34) v1(58.42,12.57) v1(58.42,9.65) v1(58.42,7.62) v1(59.44,48.26) v1(59.44,46.23) v1(59.44,14.73) v1(59.44,12.7) v1(59.44,10.67) v1(59.44,8.64) v1(59.44,6.6) v1(60.45,47.24) v1(60.45,15.75) v1(60.45,13.72) v1(60.45,11.68) v1(61.47,48.26) v1(61.47,46.23) v1(61.47,14.73) v1(61.47,12.7) v1(61.47,6.6) v1(61.98,15.24) v1(61.98,14.48) v1(61.98,13.59) v1(62.48,11.68) v1(62.99,13.59) v1(63.5,12.7) v1(63.5,10.67) v1(63.5,8.64) v1(63.5,6.6) v1(63.75,13.59) v1(64.52,13.59) v1(64.52,11.68) v1(64.52,7.62) v1(65.53,48.26) v1(65.53,46.23) v1(65.53,41.15) v1(65.53,39.12) v1(65.53,37.08) v1(65.53,12.7) v1(65.53,6.6) v1(65.79,13.59) v1(66.55,47.24) v1(66.55,40.13) v1(66.55,38.1) v1(66.55,36.07) v1(66.55,34.04) v1(66.55,13.59) v1(66.55,11.68) v1(67.31,13.59) v1(67.56,48.26) v1(67.56,46.23) v1(67.56,41.15) v1(67.56,39.12) v1(67.56,37.08) v1(67.56,35.05) v1(67.56,33.02) v1(67.56,12.7) v1(67.56,6.6) v1(68.58,47.24) v1(68.58,44.2) v1(68.58,42.16) v1(68.58,40.13) v1(68.58,38.1) v1(68.58,36.07) v1(68.58,34.04) v1(68.58,32) v1(68.58,29.97) v1(68.58,13.59) v1(68.58,11.68) v1(68.58,9.65) v1(68.58,7.62) v1(69.34,13.59) v1(69.6,46.23) v1(69.6,45.21) v1(69.6,43.18) v1(69.6,41.15) v1(69.6,39.12) v1(69.6,37.08) v1(69.6,35.05) v1(69.6,33.02) v1(69.6,30.99) v1(69.6,28.96) v1(69.6,12.7) v1(69.6,10.67) v1(69.6,8.64) v1(69.6,6.6) v1(70.1,13.59) v1(70.61,44.2) v1(70.61,42.16) v1(70.61,40.13) v1(70.61,38.1) v1(70.61,36.07) v1(70.61,34.04) v1(70.61,32) v1(70.61,29.97) v1(70.61,11.68) v1(70.61,9.65) v1(70.61,7.62) v1(71.25,13.59) v1(71.63,45.21) v1(71.63,43.18) v1(71.63,41.15) v1(71.63,39.12) v1(71.63,37.08) v1(71.63,35.05) v1(71.63,33.02) v1(71.63,30.99) v1(71.63,28.96) v1(71.63,12.7) v1(71.63,10.67) v1(71.63,8.64) v1(71.63,6.6) v1(72.01,13.59) v1(72.64,44.2) v1(72.64,42.16) v1(72.64,40.13) v1(72.64,38.1) v1(72.64,36.07) v1(72.64,34.04) v1(72.64,32) v1(72.64,29.97) v1(72.64,11.68) v1(72.64,9.65) v1(72.64,7.62) v1(72.77,13.59) v1(73.53,15.88) v1(73.53,15.11) v1(73.53,14.35) v1(73.53,13.59) v1(73.66,45.21) v1(73.66,43.18) v1(73.66,41.15) v1(73.66,39.12) v1(73.66,37.08) v1(73.66,35.05) v1(73.66,33.02) v1(73.66,30.99) v1(73.66,28.96) v1(73.66,12.7) v1(73.66,10.67) v1(73.66,8.64) v1(73.66,6.6) v1(74.68,32) v1(74.68,29.97) v1(74.68,27.94) v1(74.68,25.91) v1(74.68,23.88)
VIN: length 1.7
  TOP w0.381: TP6.1 v1(4.57,22.73)
  vias: v1(2.03,20.07) v1(2.03,19.43) v1(2.67,20.07) v1(2.67,19.43) v1(7.37,21.46) v1(7.37,20.7) v1(8.25,21.46) v1(8.25,20.7) v1(11.66,31.01) v1(11.66,30.25) v1(12.42,31.01) v1(12.42,30.25) v1(13.18,31.01) v1(13.18,30.25) v1(13.94,31.01) v1(13.94,30.25)
BOOST: length 0.2
  TOP w0.203: 9.98,13.72 9.96,13.74 U1.26
INTVCC: length 14.6
  TOP w0.203: U1.21 11.97,11.37 C1.2 12.15,11.19 R8.1 14.36,10.28 14.86,9.78 14.86,5.12 14.49,4.75 12.28,4.75 12.03,5 R5.1
PGOOD: length 47.7
  TOP w0.203: PGOOD.1 16.51,4.64 v1(16.52,4.65) ; DS3.C 9.18,25.48 v1(2.41,25.48) ; v1(6.05,6.38) 6.05,7.59 7.32,8.87 U1.14
  BOTTOM w0.203: v1(16.52,4.65) 14.8,6.38 v1(6.05,6.38) 2.51,6.38 2.03,6.86 2.03,12.83 1.27,13.59 1.27,24.33 v1(2.41,25.48)
UNNAMED_2_CAP_I32_N2: length 1.5
  TOP w0.203: C3.2 11.26,14.37 U1.27
UNNAMED_2_CAP_I45_N2: length 1.8
  TOP w0.203: R10.2 3.5,13.87 U1.3
UNNAMED_2_CAP_I46_N2: length 2.9
  TOP w0.203: U1.15 7.82,8.01 C12.2
UNNAMED_2_CAP_I48_N2: length 3.4
  TOP w0.203: C5.2 4.83,7.58 4.83,7.87 6.32,9.37 U1.12
UNNAMED_2_CAP_I51_N2: length 21.8
  TOP w0.203: C10.2 9.37,7.33 v1(9.37,8.03) 9.37,8.33 8.82,8.89 U1.17 ; IMON.1 v1(24.13,5.84)
  BOTTOM w0.203: v1(9.37,8.03) 10.03,7.37 22.61,7.37 v1(24.13,5.84)
UNNAMED_2_CAP_I80_N2: length 2
  TOP w0.381: U2.2 C14.2
UNNAMED_2_CAP_I131_N2: length 3.1
  TOP w0.381: R23.1 55.96,39.31 C22.2 54.17,39.31 U3.1
UNNAMED_2_CAP_I132_N2: length 3.1
  TOP w0.381: R22.1 55.88,35.49 C23.2 54.2,35.49 U3.6
UNNAMED_2_CN8P4PSHLD_I107_N2: length 17.4
  TOP w0.203: R22.2 57.91,35.24 D8.2 58.45,36.55 59.82,35.18 61.96,35.18 P2.2 ; D-.1 v1(63.19,29.28)
  BOTTOM w0.381: v1(63.19,29.28) 63.19,31.55 61.85,32.89 61.85,35.07 P2.2
UNNAMED_2_CN8P4PSHLD_I107_N3: length 17.6
  TOP w0.203: P2.3 61.97,39.62 59.82,39.62 58.37,38.18 D9.2 57.91,39.49 R23.2 ; D+.1 v1(63.19,45.92)
  BOTTOM w0.381: v1(63.19,45.92) 63.19,43.51 61.85,42.16 61.85,39.75 P2.3
UNNAMED_2_CNTP1P_I34_N1: length 26.2
  TOP w0.203: TP1.1 27.94,6.41 v1(27.95,6.43) ; R18.1 12.47,8 v1(11.42,8) 9.96,9.46 U1.19
  BOTTOM w0.203: v1(11.42,8) 26.38,8 v1(27.95,6.43)
UNNAMED_2_CNTP1P_I36_N1: length 14.3
  TOP w0.203: U1.13 6.82,9.18 5.41,7.77 5.41,5.78 v1(5.4,5.77) ; CLKOUT.1 v1(11.05,2.54)
  BOTTOM w0.203: v1(5.4,5.77) 5.4,3.9 6.76,2.54 v1(11.05,2.54)
UNNAMED_2_DIOLED_I7_N: length 8.3
  TOP w0.381: DS2.C 12.95,47.62 11.81,48.77 R2.2 9.09,47.58 Q1.1
UNNAMED_2_DIOLED_I7_P: length 13.8
  TOP w0.381: DS2.A v1(16.68,46.61) ; Q3.3 v1(23.04,41.73)
  BOTTOM w0.381: v1(16.68,46.61) 16.71,46.57 22.66,46.57 23.04,46.19 v1(23.04,41.73)
UNNAMED_2_DIOLED_I17_N: length 4.1
  TOP w0.381: 5.71,30.73 7.21,30.73 Q2.1 ; 5.71,30.73 4.48,30.73 DS1.C ; 5.71,30.73 R4.2
UNNAMED_2_DIOLED_I17_P: length 24.7
  TOP w0.381: v1(6.48,32) 3.14,32 2.76,31.62 DS1.A ; Q4.3 v1(24.87,33.15)
  BOTTOM w0.381: v1(24.87,33.15) 23.72,32 v1(6.48,32)
UNNAMED_2_DIOLED_I148_P: length 1.3
  TOP w0.203: R24.1 DS3.A
UNNAMED_2_DIOLED_I151_P: length 1.5
  TOP w0.381: R25.1 DS4.A
UNNAMED_2_DIOSCHOTTKY_I97_P: length 59.3
  TOP w0.381: Q2.2 7.12,28.76 R4.1 5.02,28.76 v1(4.57,29.21)
  TOP w0.635: v1(19.94,33.02) 19.94,35.39 D7.A 20.53,36.06 F1.2 20.53,47.96 21.34,48.77 33.02,48.77 34.24,47.55 D6.A
  BOTTOM w0.635: v1(19.94,33.02) 5.21,33.02 4.57,32.38 v1(4.57,29.21)
UNNAMED_2_ICLTC7103_I1_EXTVCC: length 21
  TOP w0.203: v1(11.05,10.67) 10.85,10.87 U1.20
  TOP w0.635: R9.1 v1(9.3,24.13)
  BOTTOM w0.635: v1(11.05,10.67) 12.59,10.67 13.45,11.53 13.45,23.37 12.69,24.13 v1(9.3,24.13)
UNNAMED_2_ICLTC7103_I1_FREQ: length 3.8
  TOP w0.203: U1.11 5.82,9.5 4.19,7.87 3.82,7.87 R11.2
UNNAMED_2_ICLTC7103_I1_ICTRL: length 18.4
  TOP w0.203: ICTRL.1 20.32,5.21 v1(20.33,5.22) ; U1.16 8.32,8.47 8.45,8.34 v1(8.45,8.01) 8.45,7.42 R17.1
  BOTTOM w0.203: v1(20.33,5.22) 18.69,6.86 9.6,6.86 v1(8.45,8.01)
UNNAMED_2_ICLTC7103_I1_ITH: length 11.6
  TOP w0.203: v1(13.06,8.59) 12.34,8.59 R8.2 ; v1(4.27,10.63) 4.51,10.87 U1.9
  BOTTOM w0.203: v1(4.27,10.63) 6.31,8.59 v1(13.06,8.59)
UNNAMED_2_ICLTC7103_I1_OVLO: length 2
  TOP w0.203: U1.7 4.65,11.87 4.05,12.47 R10.1
UNNAMED_2_ICLTC7103_I1_RIND: length 1.6
  TOP w0.203: R16.1 3.61,11.37 U1.8
UNNAMED_2_ICLTC7103_I1_VFB: length 3.1
  TOP w0.203: R12.1 3.58,8.64 R13.1 4.43,9.93 4.87,10.37 U1.10
UNNAMED_2_ICLTC7103_I1_VPRG1: length 4.4
  TOP w0.203: R5.2 R6.1 10.8,7.23 10.8,7.72 9.32,9.2 U1.18
UNNAMED_2_LINLT8302_I70_EN: length 2
  TOP w0.381: R15.1 28.24,21.91 U2.1
UNNAMED_2_LINLT8302_I70_RFB: length 2.1
  TOP w0.381: U2.6 38.03,19.37 R20.2
UNNAMED_2_LINLT8302_I70_RREF: length 6.4
  TOP w0.381: U2.7 R21.2 38.61,20.64 38.99,21.02 38.99,23.09 38.61,23.47 R14.2
UNNAMED_2_LINLT8302_I70_TC: length 2.2
  TOP w0.381: U2.8 37.82,21.91 R21.1
UNNAMED_2_RES_I9_N1: length 16.9
  TOP w0.381: R1.1 22.47,45.72 v1(21.84,45.72) ; Q1.3 9.5,45.72 v1(9.78,45.72)
  TOP w0.508: R1.1 24.58,46.06 Q3.1
  BOTTOM w0.381: v1(9.78,45.72) v1(21.84,45.72)
UNNAMED_2_RES_I19_N1: length 25.7
  TOP w0.381: R3.1 v1(22.81,39.83) ; v1(9.91,34.42) 9.91,30.25 Q2.3
  TOP w0.508: Q4.1 24.58,38.7 R3.1
  BOTTOM w0.381: v1(22.81,39.83) 22.81,35.51 21.72,34.42 v1(9.91,34.42)
UNNAMED_2_RES_I19_N2: length 30.1
  TOP w0.508: R3.2 24.35,37.2 Q4.2 ; R1.2 24.35,44.56 Q3.2
  TOP w0.635: Q3.4 Q4.4 ; Q4.4 31.38,36.46 D6.C 34.26,36.44 D2.C ; Q4.4 Q4.2
  TOP w1.016: Q3.2 Q3.4
V_ENTRY: length 4.6
  TOP w0.635: 2.41,40.23 P1.1 ; P1.1 3.56,39.09 ; P1.1 3.56,41.38 ; P1.1 4.7,40.23
VOUT: length 8.5
  TOP w0.203: D5.C 72.25,17.89
  TOP w0.381: C21.2 52.53,34.79 U3.5 ; v1(72.08,26.29) 72.08,27.16 R25.2
  TOP w0.635: 62.22,33.91 P2.1 ; P2.1 63.19,32.94 ; P2.1 64.16,33.91 ; 59.6,33.91 P2.5 ; P2.5 61.54,33.91 ; P2.5 60.57,32.94
  vias: v1(55.75,33.91) v1(55.75,33.15) v1(56.52,33.91) v1(56.52,33.15) v1(71.76,21.46) v1(71.76,20.7) v1(71.76,19.81) v1(72.52,21.46) v1(72.52,20.7) v1(72.52,19.81)
VOUT_7103: length 29.1
  TOP w0.203: R12.2 v1(2.67,8.01) ; R24.2 13.05,25.5 13.05,24.11
  TOP w0.381: C7.2 27.5,19.37 U2.3
  BOTTOM w0.203: v1(11.68,23.11) 11.68,13.97 11.05,13.34 3.43,13.34 2.67,12.58 v1(2.67,8.01)

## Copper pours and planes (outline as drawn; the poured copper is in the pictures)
GND on TOP: 0.84,49.53 46.74,49.53 46.74,1.27 0.84,1.27 0.84,16.38 4.19,16.38 4.19,21.08 3.94,21.34 0.84,21.34 ; 13 cut-outs
GND on BOTTOM: 0.84,49.53 46.74,49.53 46.74,1.27 0.84,1.27 0.84,16.38 0.76,16.38 0.76,21.34 0.84,21.34 0.84,23.75 3.3,23.75 3.3,24.89 3.43,24.89 3.43,26.04 2.41,26.04 2.41,25.15 0.84,25.15
GND on L2_GND, L3_GND: 0.83,49.53 46.74,49.53 46.74,1.27 0.83,1.27
PGND on TOP: 50.67,49.53 74.93,49.53 74.93,1.27 50.67,1.27 50.67,16.13 60.83,16.13 60.83,19.43 50.67,19.43 ; 1 cut-out
PGND on BOTTOM: 50.67,49.53 74.93,49.53 74.93,1.27 50.67,1.27
PGND on L2_GND, L3_GND: 50.67,49.53 75.18,49.53 75.18,1.27 50.67,1.27
VIN on TOP: 14.35,30.23 14.35,37.34 11.3,37.34 11.3,30.23 11.56,29.97 14.1,29.97
VIN on TOP: 2.79,20.45 1.91,20.45 1.65,20.19 1.65,17.78 3.05,17.78 3.05,20.19
VIN on TOP: 7.11,21.72 8.89,21.72 9.02,21.59 9.02,15.24 7.75,15.24 7.75,17.4 6.99,18.16 6.99,21.59
VIN on BOTTOM: 7.75,31.24 14.22,31.24 14.22,29.08 8.89,29.08 6.35,26.54 6.35,23.88 8.51,21.72 8.51,19.43 8.25,19.18 1.91,19.18 1.78,19.3 1.78,21.72 3.94,23.88 3.94,27.43
BOOST on TOP: 14.73,14.99 21.08,14.99 21.08,11.81 15.81,11.81 14.8,12.83 9.65,12.83 9.65,13.84 10.41,13.84 10.54,13.72 12.07,13.72 12.32,13.97 13.72,13.97
UNNAMED_2_CAP_I45_N2 on TOP: 4.71,13.78 4.71,15.35 4.45,15.62 1.77,15.62 1.77,13.78
UNNAMED_2_CAP_I86_N1 on TOP: 39.12,32.13 39.12,28.83 43.31,28.83 43.31,32.13
UNNAMED_2_DIO_I82_N on TOP: 37.97,28.07 37.97,25.65 43.31,25.65 43.31,28.07
UNNAMED_2_DIOSCHOTTKY3P_I89_A1 on TOP: 50.67,25.02 50.67,19.81 59.94,19.81 59.94,25.02
UNNAMED_2_DIOSCHOTTKY_I83_P on TOP: 44.2,32.13 46.74,32.13 46.74,17.02 36.32,17.02 35.31,18.03 35.31,18.29 42.93,18.29 44.2,19.56
V_ENTRY on TOP: 10.92,44.96 14.35,44.96 14.35,38.48 1.27,38.48 1.27,41.91 10.92,41.91
VOUT on TOP: 64.64,33.02 64.64,34.16 53.34,34.16 52.96,34.54 52.96,35.05 52.45,35.05 52.45,32.64 56.52,32.64 57.15,33.27 59.05,33.27 59.82,32.51 64.14,32.51
VOUT on TOP: 74.93,21.21 74.93,17.65 74.3,17.02 61.59,17.02 61.59,25.02 65.79,25.02 68.96,21.84 74.3,21.84
VOUT on BOTTOM: 55.63,34.16 56.64,34.16 56.9,33.91 56.9,30.1 60.45,26.54 72.26,26.54 72.77,26.04 72.77,19.43 71.5,19.43 71.5,24 70.36,25.15 59.82,25.15 55.37,29.59 55.37,33.91
VOUT_7103 on TOP: 18.03,32.26 27.05,32.26 27.05,27.3 27.69,26.67 33.02,26.67 33.53,27.18 33.53,32.13 38.35,32.13 38.35,29.08 36.7,29.08 36.32,28.7 36.32,26.54 37.72,25.15 40.77,25.15 41.4,24.51 41.4,22.35 39.62,22.35 39.62,23.75 39.12,24.26 37.08,24.26 36.58,24.77 28.07,24.77 27.05,23.75 27.05,21.59 25.78,21.59 25.78,19.68 27.56,19.68 27.69,19.56 27.69,18.03 24.51,18.03 23.24,19.3 23.24,21.97 15.52,21.97 15.02,22.47 11.25,22.47 11.25,24.49 17.46,24.49 18.03,25.06

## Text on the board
User.Comments: INSTALL SCREW (M035074) ON TOP AND STANDOFF (M025337) ON BOTTOM AT 4 LOCATIONS
Ref Des/Assembly Top: A | C | +
Ref Des/Silkscreen Top: A | C | EVAL-CN0509-EBZ | LOWER PORT | DCP ENABLED
PAGE_OUTLINE: 18MAR20 | B | CHANGES AS PER ECR-099081 | 29OCT20 | T.CABILDO | EVAL-CN0509-EBZ
DIMENSION: - | " " | (REF) | DIA MAX
User.17: L2 GND | 08-      -06
User.18: L3 GND | 08-      -07
User.45: FIGURE | SIZE | 10.0 | 36.0 | 50.0 | 91.0 | 125.0 | PLATED | NON-PLATED | FINISHED HOLES IN MILS | ALL UNITS ARE IN MILS | QTY | 614 | 8 | 2 | 4 | TOLERANCE/NOTES
